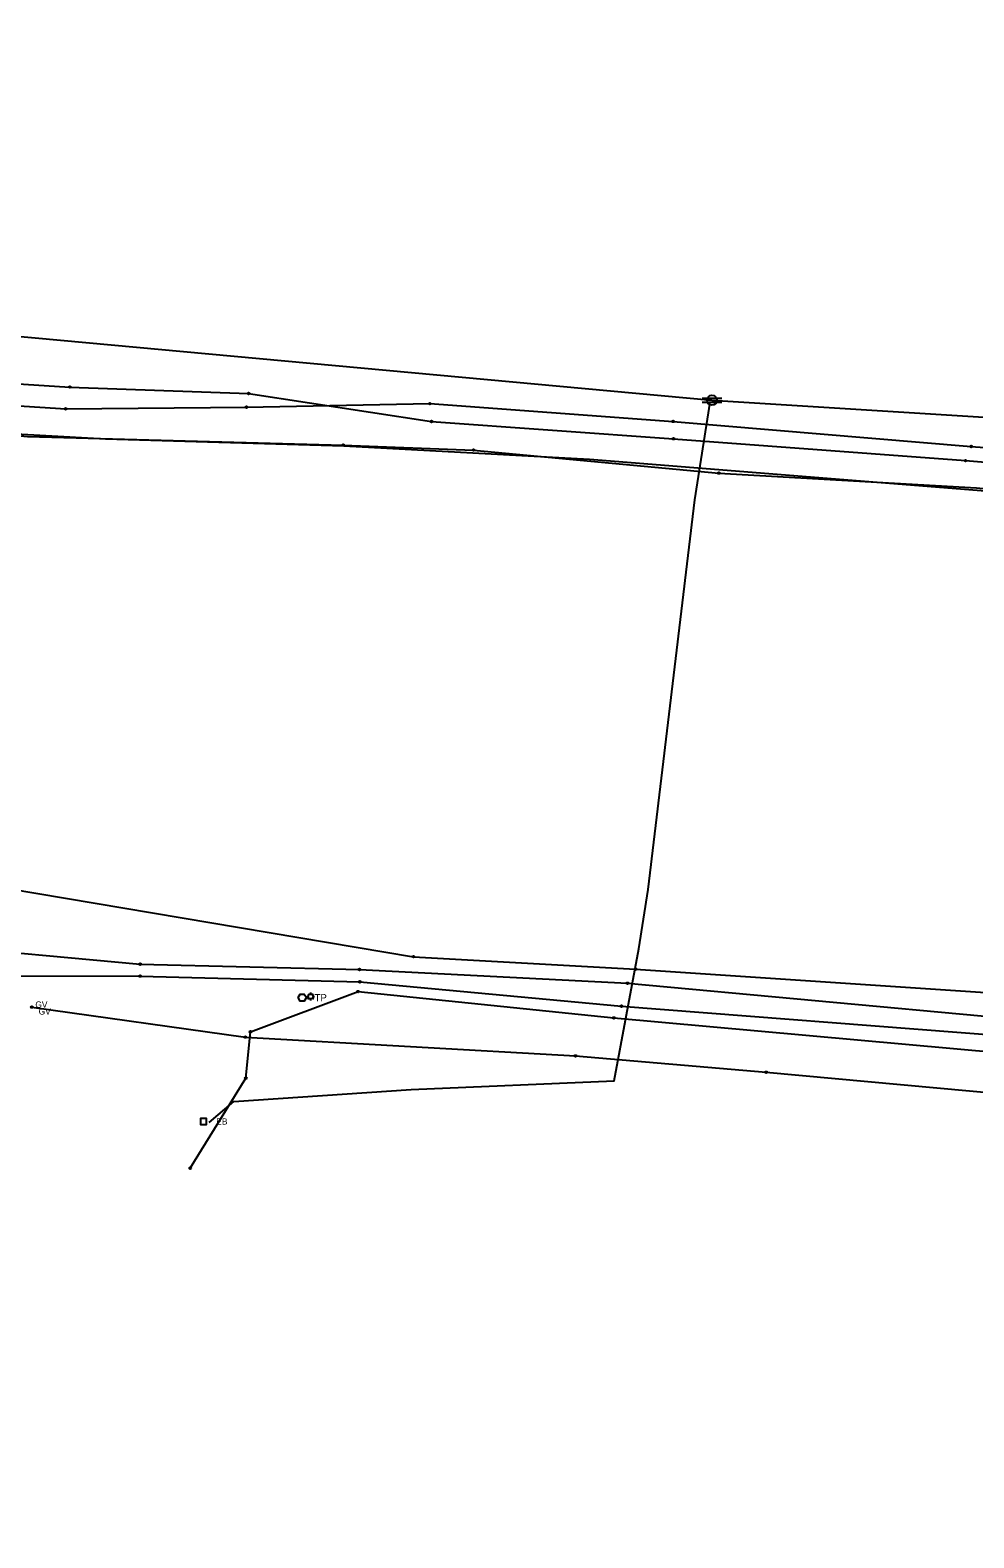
# Model space of a CAD drawing. Extents: x 20500343 to 20505311, y 7953484 to 7954193.
# Drawn here: x 20504268.9 to 20504479.4, y 7953484.1 to 7953820.7 of the extents above; entities that cross this region are included whole.
import ezdxf

# ---------------------------------------------------------------- set-up
doc = ezdxf.new("R2010")
doc.units = 0
for name, color, linetype in [('C-PROP-LINE-LOT', 7, 'Continuous'), ('V-ANNO-BNDY', 7, 'Continuous'), ('V-ANNO-NOTE', 7, 'Continuous'), ('V-CTRL-HVPT', 7, 'Continuous'), ('V-MON-FND', 7, 'Continuous'), ('V-SITE-FENC', 7, 'Continuous')]:
    doc.layers.add(name, color=color, linetype=linetype)

msp = doc.modelspace()

# ---------------------------------------------------------------- linework, layer by layer
at = {"layer": 'C-PROP-LINE-LOT'}
for points in [[(20503437.68, 7953820.69), (20503685.54, 7953801.97), (20503900.73, 7953784.06), (20504174.6, 7953760.81), (20504420.99, 7953738.08), (20504670.9, 7953722.47), (20504838.2, 7953713.61), (20505006.28, 7953702.11), (20505174.11, 7953700.54)], [(20503790.68, 7953784.4), (20503808.98, 7953784.03), (20503909.45, 7953778.06), (20503959.38, 7953770.95), (20504045.88, 7953760.22), (20504085.92, 7953755.66), (20504130.44, 7953752.67), (20504154.9, 7953748.08), (20504187.24, 7953745.87), (20504215.5, 7953745), (20504277.71, 7953741.02), (20504317.61, 7953739.57), (20504358.43, 7953733.33), (20504412.41, 7953729.48), (20504477.58, 7953724.58), (20504548.69, 7953718.7), (20504593.57, 7953715.94), (20504642.65, 7953712.07), (20504674.79, 7953710.13), (20504682, 7953710.89), (20504686.23, 7953720.21)], [(20503699.26, 7953775.1), (20503803.54, 7953764.58), (20503866.33, 7953759.03), (20503928.53, 7953761.61), (20504053.64, 7953746.16), (20504141.91, 7953734.18), (20504242.25, 7953732.31), (20504268.23, 7953730.01), (20504338.72, 7953728.07), (20504367.8, 7953726.96), (20504422.51, 7953721.81), (20504479.99, 7953718.52), (20504541.43, 7953712.4), (20504605.71, 7953707.78), (20504671.49, 7953704.84), (20504755.78, 7953700.92), (20504815.67, 7953699.69), (20504872.03, 7953696.31), (20505039.13, 7953696.21), (20505092.16, 7953700.52), (20505136.96, 7953703.53), (20505186.48, 7953709.16)], [(20503774.54, 7953770.56), (20503865.82, 7953759.32), (20503909.8, 7953760.07), (20503935.64, 7953762.61), (20504004.9, 7953753.63), (20504052.71, 7953745.8), (20504101.86, 7953738.14), (20504128.8, 7953735.15), (20504243.01, 7953731.82), (20504285.64, 7953729.43), (20504338.85, 7953727.9), (20504393.63, 7953724.94), (20504522.96, 7953714.6), (20504559.53, 7953710.68), (20504601.53, 7953709.61)], [(20504210.51, 7953740.4), (20504276.78, 7953736.15), (20504317.11, 7953736.51), (20504358.06, 7953737.31), (20504412.3, 7953733.34), (20504478.84, 7953727.73), (20504548.56, 7953722.54), (20504593.65, 7953719.05), (20504644.38, 7953715.53), (20504690.36, 7953713.78), (20504723.6, 7953712.89), (20504765.96, 7953712.31), (20504818.14, 7953709.88), (20504868.03, 7953706.56), (20504918.85, 7953702.08), (20504975.03, 7953699.08), (20505009.69, 7953697.2), (20505013.14, 7953700.37), (20505013.9, 7953705.42)], [(20504308.83, 7953576.82), (20504314.33, 7953581.53), (20504353.88, 7953584.18), (20504399.2, 7953586.1), (20504404.67, 7953615.6), (20504406.76, 7953628.82), (20504417.19, 7953715.84), (20504420.58, 7953737.66)], [(20504024.77, 7953669.37), (20504354.36, 7953613.84), (20504403.94, 7953611.06), (20504480.92, 7953605.95), (20504541.55, 7953600.29), (20504620.66, 7953595.28), (20504701.53, 7953590.77), (20504892.22, 7953579.68), (20504974.75, 7953574.83)], [(20504246.56, 7953616.51), (20504293.41, 7953612.16), (20504342.32, 7953610.98), (20504402.14, 7953607.9), (20504485.85, 7953600.21), (20504541.12, 7953597.7), (20504568.97, 7953596.35), (20504645.79, 7953589.23), (20504701.93, 7953586.24), (20504764.32, 7953586.16), (20504836, 7953579.91), (20504942.46, 7953569.69), (20504990.68, 7953565.15)], [(20504245.01, 7953609.59), (20504293.38, 7953609.52), (20504342.41, 7953608.24), (20504400.78, 7953602.78), (20504485.23, 7953596.26), (20504540.28, 7953594.35), (20504568.66, 7953593.24), (20504644.38, 7953584.7), (20504700.91, 7953581.94), (20504764.05, 7953583.43), (20504836, 7953575.34), (20504894.29, 7953574.48), (20504941.93, 7953567.42), (20504990.58, 7953562.23)], [(20504304.58, 7953566.63), (20504316.99, 7953586.74), (20504318.02, 7953597.08), (20504342.01, 7953606.04), (20504399.08, 7953600.17), (20504485.6, 7953592.38), (20504540.92, 7953587.54), (20504567.5, 7953585.67), (20504644.21, 7953580.53), (20504700.38, 7953577.98), (20504764.23, 7953578.75), (20504836.1, 7953570.47), (20504894.11, 7953571.81), (20504941.45, 7953564.86), (20504990.37, 7953560.12)], [(20504269.22, 7953602.59), (20504316.87, 7953595.9), (20504390.54, 7953591.68), (20504433.07, 7953588.04), (20504524.61, 7953579.67), (20504571.19, 7953575.9), (20504651.75, 7953571.77), (20504777.78, 7953566.7), (20504848.38, 7953562.34), (20504918.92, 7953559.08), (20504984.04, 7953555.83), (20505049.37, 7953553.38), (20505120.36, 7953550.4), (20505152.31, 7953547.69), (20505196.06, 7953544.59), (20505233.38, 7953543.22), (20505244.11, 7953538.95), (20505270.71, 7953516.66), (20505302.37, 7953489.32), (20505310.32, 7953484.09)]]:
    msp.add_lwpolyline(points, dxfattribs=at)
at = {"layer": 'V-ANNO-NOTE'}
for centre in [(20504277.71, 7953741.02), (20504317.61, 7953739.57), (20504358.06, 7953737.31), (20504276.78, 7953736.15), (20504317.11, 7953736.51), (20504358.43, 7953733.33), (20504412.3, 7953733.34), (20504338.72, 7953728.07), (20504367.8, 7953726.96), (20504412.41, 7953729.48), (20504478.84, 7953727.73), (20504477.58, 7953724.58), (20504422.51, 7953721.81), (20504293.41, 7953612.16), (20504354.36, 7953613.84), (20504293.38, 7953609.52), (20504342.32, 7953610.98), (20504403.94, 7953611.06), (20504342.01, 7953606.04), (20504342.41, 7953608.24), (20504402.14, 7953607.9), (20504269.22, 7953602.59), (20504400.78, 7953602.78), (20504399.08, 7953600.17), (20504316.87, 7953595.9), (20504318.02, 7953597.08), (20504390.54, 7953591.68), (20504316.99, 7953586.74), (20504433.07, 7953588.04), (20504304.58, 7953566.63)]:
    msp.add_circle(centre, 0.2, dxfattribs=at)
at = {"layer": 'V-CTRL-HVPT'}
for p, q in [((20504418.79, 7953738.53), (20504423.19, 7953738.53)), ((20504418.79, 7953737.65), (20504423.19, 7953737.65)), ((20504330.82, 7953605.58), (20504331.05, 7953605.35)), ((20504331.43, 7953605.83), (20504331.43, 7953605.51)), ((20504331.81, 7953605.35), (20504332.04, 7953605.58)), ((20504330.56, 7953604.96), (20504330.89, 7953604.96)), ((20504330.82, 7953604.35), (20504331.05, 7953604.58)), ((20504331.43, 7953604.42), (20504331.43, 7953604.09)), ((20504331.81, 7953604.58), (20504332.04, 7953604.35)), ((20504331.97, 7953604.96), (20504332.3, 7953604.96))]:
    msp.add_line(p, q, dxfattribs=at)
for centre, radius in [((20504420.99, 7953738.08), 1.1), ((20504331.43, 7953604.96), 0.543)]:
    msp.add_circle(centre, radius, dxfattribs=at)
at = {"layer": 'V-MON-FND'}
msp.add_lwpolyline([(20504328.66, 7953604.7), (20504329.11, 7953605.49), (20504330.03, 7953605.49), (20504330.48, 7953604.7), (20504330.03, 7953603.91), (20504329.11, 7953603.91), (20504328.66, 7953604.7)], dxfattribs=at)
at = {"layer": 'V-SITE-FENC'}
msp.add_lwpolyline([(20504307.54, 7953576.38), (20504307.54, 7953576.38), (20504308.23, 7953576.38), (20504308.23, 7953577.75), (20504306.85, 7953577.75), (20504306.85, 7953576.38), (20504307.54, 7953576.38)], dxfattribs=at)

# ---------------------------------------------------------------- texts
at = {"layer": 'V-ANNO-BNDY'}
for p in [(20504270.01, 7953602.45), (20504270.75, 7953600.91)]:
    msp.add_text('GV', height=1.399, dxfattribs=at).set_placement(p)
at = {"layer": 'V-MON-FND'}
msp.add_text('TP', height=1.599, dxfattribs=at).set_placement((20504332.31, 7953603.9))
at = {"layer": 'V-SITE-FENC'}
msp.add_text('EB', height=1.399, dxfattribs=at).set_placement((20504310.38, 7953576.36))

doc.saveas('drawing.dxf')
